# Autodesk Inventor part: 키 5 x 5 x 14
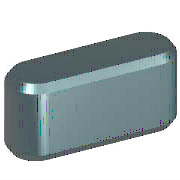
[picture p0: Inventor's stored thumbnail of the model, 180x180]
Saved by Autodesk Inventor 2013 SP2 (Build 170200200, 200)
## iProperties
IsCustomPart: 1
Created: 2012-02
Part Number: 키 5 x 5 x 14
Material: 강철, 연강
Description: 키 및 해당 키홈
Document SubType Name: Modeling
Standard: KS B 1311
Designer: mduedu
Standards Organization: KS
Language: ko-KR
Size Designation: 4 x 4 x 12
Categories: <MemberInstance><Categories><Category DisplayName="샤프트 부품" InternalName="7f7aeb1f-a693-4053-b835-cee3144e0d98" Mnemonic="SHFT"><Category DisplayName="키" Interna
Density: 1 g/cm^3
Author: mduedu
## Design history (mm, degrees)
workplane "Work Plane1"
workplane "Work Plane2"
sketch "스케치1"
  geometry: L1 (2.5, 2.5)-(11.5, 2.5); L2 (11.5, -2.5)-(2.5, -2.5); L3 (0, 8.9)-(0, -4.4) reference; L4 (-2.8, 0)-(16.8, 0) reference; L5 (14, 0)-(14, 7); A1 r 2.5 centre (2.5, 0) between (2.5, 2.5) and (2.5, -2.5); A2 r 2.5 centre (11.5, 0) between (11.5, -2.5) and (11.5, 2.5)
  constraints: 6 end point, 5 point on circle, 4 tangent, 3 point on line, 2 centre point, 1 horizontal, 1 parallel, 1 perpendicular
  dimensions: "d0" = 2.5 radius of A1 (= 0.5 x PB); "d13" = 2.5 radius of A2 (= 0.5 x PB); "d14" = 14 distance between parallel lines of L5 L3 (= NLG)
extrude "본체1" new body sketch "스케치1" taper "d3" = 0 deg; stored distance "d4" = 10
workplane "Work Plane3"
body "Solid1"
chamfer "모따기1" distance "d8" = 0.25 (= PHH); stored, may be unused: second distance "d9" = 0.25 (= PHH), angle "d15" = 45 deg
other parameters: "d1" = -3 (= -PNT), "d2" = 2 (= PH - PNT), "NLG" = 14 [user parameter; used in 3 equation terms], "PB" = 5 [user parameter; used in 2 equation terms], "PNT" = 3 [user parameter; used in 2 equation terms], "PH" = 5 [user parameter; used in 1 equation term], "PHH" = 0.25 [user parameter; used in 2 equation terms], "d10" = 0, "d16" = 0, "d17" = 0, "d18" = 0, "PLB2" = 14 (= NLG) [user parameter], "WDMAX" = 12 [user parameter], "PLB1" = 14 (= NLG) [user parameter], "RR" = 0.08 [user parameter], "PUEB" = 1.8 [user parameter]
